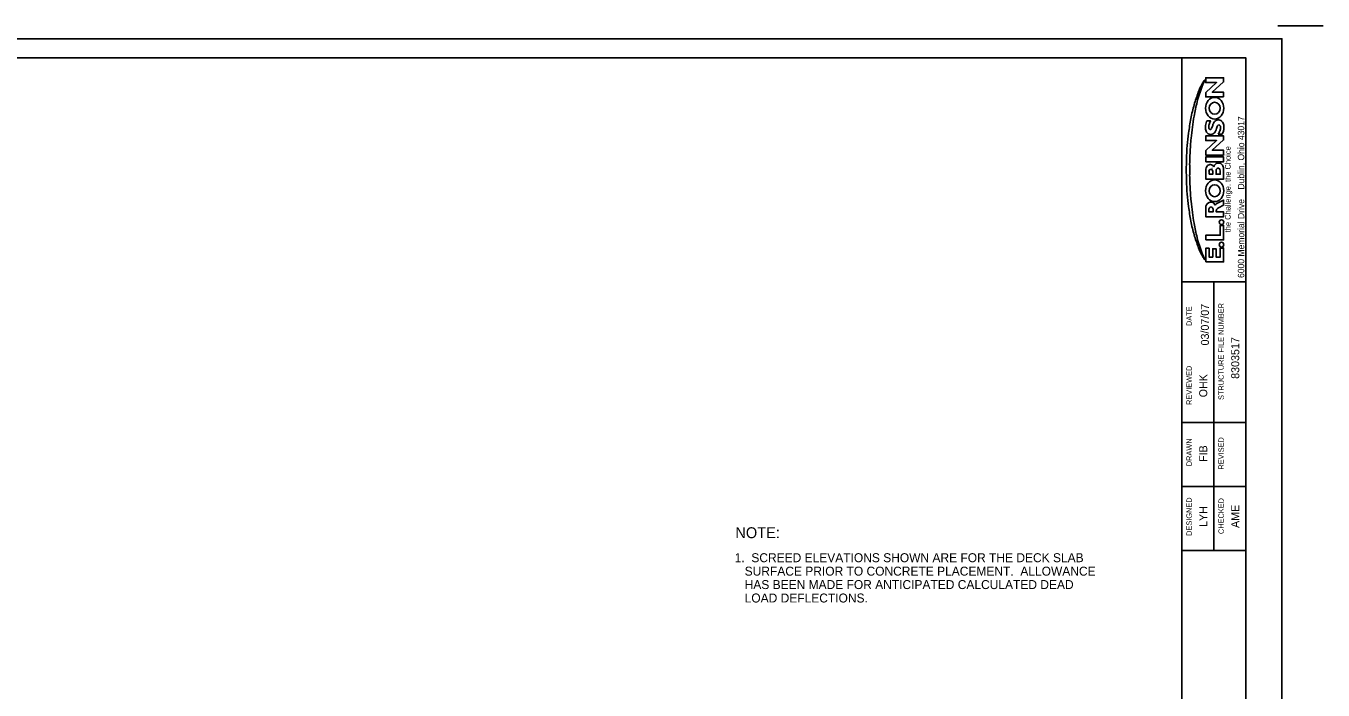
# Model space of a CAD drawing. Extents: x 1466871.1 to 1466907, y 570850.5 to 570872.5.
# Drawn here: x 1466886.76 to 1466907.02, y 570862.08 to 570872.46 of the extents above; entities that cross this region are included whole.
import ezdxf

# ---------------------------------------------------------------- set-up
doc = ezdxf.new("R2010")
doc.units = 0
for name, color, linetype in [('BR_P_Gen_Text', 7, 'Continuous'), ('SH_Border', 7, 'Continuous'), ('SH_Cut_Line', 7, 'Continuous'), ('SH_Data', 7, 'Continuous')]:
    doc.layers.add(name, color=color, linetype=linetype)

msp = doc.modelspace()

# ---------------------------------------------------------------- linework, layer by layer
at = {"layer": 'BR_P_Gen_Text'}
for p, q in [((1466905.443, 570870.773), (1466905.381, 570870.773)), ((1466905.381, 570870.773), (1466905.443, 570870.773)), ((1466905.187, 570870.07), (1466905.187, 570870.205)), ((1466905.238, 570870.19), (1466905.238, 570870.145)), ((1466905.238, 570870.145), (1466905.238, 570870.19)), ((1466905.465, 570870.22), (1466905.465, 570870.07)), ((1466905.465, 570870.07), (1466905.187, 570870.07)), ((1466905.237, 570869.6), (1466905.237, 570869.557)), ((1466905.237, 570869.557), (1466905.237, 570869.6)), ((1466905.237, 570869.557), (1466905.301, 570869.557)), ((1466905.301, 570869.557), (1466905.237, 570869.557)), ((1466905.301, 570869.557), (1466905.301, 570869.6)), ((1466905.301, 570869.6), (1466905.301, 570869.557)), ((1466905.465, 570869.66), (1466905.384, 570869.621)), ((1466905.384, 570869.621), (1466905.465, 570869.66))]:
    msp.add_line(p, q, dxfattribs=at)
for points in [[(1466905.465, 570871.354), (1466905.187, 570871.354), (1466905.187, 570871.423), (1466905.355, 570871.579), (1466905.187, 570871.579), (1466905.187, 570871.654), (1466905.465, 570871.654), (1466905.465, 570871.589), (1466905.288, 570871.428), (1466905.465, 570871.428)], [(1466905.465, 570870.446), (1466905.187, 570870.446), (1466905.187, 570870.515), (1466905.355, 570870.671), (1466905.187, 570870.671), (1466905.187, 570870.745), (1466905.465, 570870.745), (1466905.465, 570870.681), (1466905.288, 570870.52), (1466905.465, 570870.52)], [(1466905.187, 570870.342), (1466905.187, 570870.416), (1466905.465, 570870.416), (1466905.465, 570870.342)], [(1466905.187, 570868.774), (1466905.187, 570868.989), (1466905.238, 570868.989), (1466905.238, 570868.85), (1466905.295, 570868.85), (1466905.295, 570868.981), (1466905.347, 570868.981), (1466905.347, 570868.85), (1466905.414, 570868.85), (1466905.414, 570868.992), (1466905.465, 570868.992), (1466905.465, 570868.774)]]:
    msp.add_lwpolyline(points, close=True, dxfattribs=at)
for points in [[(1466905.205, 570870.981), (1466905.26, 570870.981), (1466905.249, 570870.954)], [(1466905.249, 570870.954), (1466905.26, 570870.981), (1466905.205, 570870.981)], [(1466905.465, 570870.22), (1466905.465, 570870.07), (1466905.187, 570870.07), (1466905.187, 570870.205)], [(1466905.187, 570870.205), (1466905.187, 570870.07), (1466905.465, 570870.07)], [(1466905.238, 570870.145), (1466905.297, 570870.145), (1466905.297, 570870.19)], [(1466905.297, 570870.19), (1466905.297, 570870.145), (1466905.238, 570870.145)], [(1466905.348, 570870.199), (1466905.348, 570870.145), (1466905.414, 570870.145), (1466905.414, 570870.199)], [(1466905.414, 570870.199), (1466905.414, 570870.145), (1466905.348, 570870.145), (1466905.348, 570870.199)], [(1466905.465, 570870.07), (1466905.465, 570870.22)], [(1466905.401, 570869.71), (1466905.465, 570869.742), (1466905.465, 570869.66)], [(1466905.465, 570869.66), (1466905.465, 570869.742), (1466905.401, 570869.71)], [(1466905.352, 570869.579), (1466905.352, 570869.557), (1466905.465, 570869.557), (1466905.465, 570869.482), (1466905.187, 570869.482), (1466905.187, 570869.557), (1466905.187, 570869.621)], [(1466905.187, 570869.621), (1466905.187, 570869.557), (1466905.187, 570869.482), (1466905.465, 570869.482)], [(1466905.237, 570869.6), (1466905.237, 570869.557), (1466905.301, 570869.557), (1466905.301, 570869.6)], [(1466905.465, 570869.482), (1466905.465, 570869.557), (1466905.352, 570869.557), (1466905.352, 570869.579)], [(1466905.187, 570869.118), (1466905.187, 570869.193), (1466905.414, 570869.193), (1466905.414, 570869.345), (1466905.465, 570869.345), (1466905.465, 570869.118), (1466905.187, 570869.118)], [(1466905.465, 570869.345), (1466905.414, 570869.345), (1466905.414, 570869.193), (1466905.187, 570869.193), (1466905.187, 570869.118)], [(1466905.187, 570869.118), (1466905.465, 570869.118), (1466905.465, 570869.345)]]:
    msp.add_lwpolyline(points, dxfattribs=at)
for centre, major_axis, ratio, start_param, end_param in [((1466905.95, 570870.947), (0, 1.141), 0.85, 0.988431, 1.105191), ((1466905.95, 570870.947), (0, 1.141), 0.85, 0.988431, 1.105191), ((1466866.685, 570892.721), (0, 49.953), 0.85, 4.274094, 4.276309), ((1466866.685, 570892.721), (0, 49.953), 0.85, 4.274094, 4.276309), ((1466905.397, 570871.375), (0, 0.363), 0.85, 0.822588, 0.988431), ((1466905.397, 570871.375), (0, 0.363), 0.85, 0.822588, 0.988431), ((1466907.502, 570870.201), (0, 3.112), 0.85, 1.165908, 1.233316), ((1466907.502, 570870.201), (0, 3.112), 0.85, 1.165908, 1.233316), ((1466906.428, 570870.806), (0, 1.685), 0.85, 1.132502, 1.288747), ((1466906.428, 570870.806), (0, 1.685), 0.85, 1.132502, 1.288747), ((1466905.526, 570871.197), (0, 0.583), 0.85, 1.105191, 1.165908), ((1466905.526, 570871.197), (0, 0.583), 0.85, 1.105191, 1.165908), ((1466906.711, 570870.549), (0, 2.119), 0.85, 1.243005, 1.347881), ((1466906.711, 570870.549), (0, 2.119), 0.85, 1.243005, 1.347881), ((1466907.926, 570870.296), (0, 3.52), 0.85, 1.288747, 1.354281), ((1466907.926, 570870.296), (0, 3.52), 0.85, 1.288747, 1.354281), ((1466905.326, 570871.177), (0, -0.0938), 0.910305, 4.71238898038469, 4.712389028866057), ((1466907.9, 570870.279), (0, 3.544), 0.85, 1.360764, 1.426378), ((1466907.9, 570870.279), (0, 3.544), 0.85, 1.360764, 1.426378), ((1466909.145, 570870.102), (0, 4.963), 0.85, 1.378198, 1.448475), ((1466909.145, 570870.102), (0, 4.963), 0.85, 1.378198, 1.448475), ((1466905.357, 570870.878), (0, 0.206), 0.85, 1.108668, 1.320154), ((1466905.357, 570870.878), (0, 0.206), 0.85, 1.108668, 1.320154), ((1466905.066, 570871.048), (0, 0.176), 0.85, 4.250261, 4.3216), ((1466905.066, 570871.048), (0, 0.176), 0.85, 4.250261, 4.3216), ((1466905.399, 570870.868), (0, 0.196), 0.85, 1.114999, 1.297264), ((1466905.399, 570870.868), (0, 0.196), 0.85, 1.114999, 1.297264), ((1466905.484, 570870.822), (0, 0.238), 0.85, 1.030221, 1.254809), ((1466905.484, 570870.822), (0, 0.238), 0.85, 1.030221, 1.254809), ((1466905.39, 570870.888), (0, 0.11), 0.85, 0.486829, 1.030221), ((1466905.39, 570870.888), (0, 0.11), 0.85, 0.486829, 1.030221), ((1466905.326, 570871.177), (0, -0.17), 0.841969, 0, 4.84813681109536e-08), ((1466905.377, 570870.918), (0, 0.0761), 0.85, 0.083326, 0.486829), ((1466905.377, 570870.918), (0, 0.0761), 0.85, 0.083326, 0.486829), ((1466905.383, 570870.841), (0, 0.154), 0.85, 6.083659, 6.366511), ((1466905.383, 570870.841), (0, 0.154), 0.85, 6.083659, 6.366511), ((1466905.396, 570870.919), (0, 0.0741), 0.85, 5.529173, 6.083659), ((1466905.396, 570870.919), (0, 0.0741), 0.85, 5.529173, 6.083659), ((1466905.376, 570870.893), (0, 0.109), 0.85, 4.887723, 5.529173), ((1466905.376, 570870.893), (0, 0.109), 0.85, 4.887723, 5.529174), ((1466906.48, 570870.456), (0, 1.866), 0.85, 1.391456, 1.496401), ((1466906.48, 570870.456), (0, 1.866), 0.85, 1.391456, 1.496401), ((1466905.344, 570870.881), (0, 0.19), 0.85, 1.320154, 1.737094), ((1466905.344, 570870.881), (0, 0.19), 0.85, 1.320154, 1.737094), ((1466905.277, 570870.868), (0, 0.11), 0.85, 1.737094, 2.325359), ((1466905.277, 570870.868), (0, 0.11), 0.85, 1.737094, 2.325359), ((1466905.256, 570870.845), (0, 0.0764), 0.85, 2.325359, 2.878408), ((1466905.256, 570870.845), (0, 0.0764), 0.85, 2.325359, 2.878408), ((1466905.329, 570870.89), (0, 0.111), 0.85, 1.456901, 1.818883), ((1466905.329, 570870.89), (0, 0.111), 0.85, 1.456901, 1.818883), ((1466905.332, 570870.89), (0, 0.115), 0.85, 1.297264, 1.456901), ((1466905.332, 570870.89), (0, 0.115), 0.85, 1.297264, 1.456901), ((1466905.26, 570870.87), (0, 0.0279), 0.85, 1.818883, 2.384672), ((1466905.26, 570870.87), (0, 0.0279), 0.85, 1.818883, 2.384672), ((1466905.264, 570870.881), (0, 0.113), 0.85, 2.878408, 3.55749), ((1466905.264, 570870.881), (0, 0.113), 0.85, 2.878408, 3.55749), ((1466905.255, 570870.864), (0, 0.0197), 0.85, 2.384672, 3.137191), ((1466905.255, 570870.864), (0, 0.0197), 0.85, 2.384672, 3.137191), ((1466905.255, 570870.872), (0, 0.0276), 0.85, 3.137191, 4.01614), ((1466905.255, 570870.872), (0, 0.0276), 0.85, 3.137191, 4.01614), ((1466905.227, 570870.899), (0, 0.071), 0.85, 4.01614, 4.175459), ((1466905.227, 570870.899), (0, 0.071), 0.85, 4.01614, 4.175459), ((1466905.158, 570870.948), (0, 0.165), 0.85, 4.175459, 4.396402), ((1466905.158, 570870.948), (0, 0.165), 0.85, 4.175459, 4.396402), ((1466905.277, 570870.845), (0, 0.0738), 0.85, 3.55749, 3.971659), ((1466905.277, 570870.845), (0, 0.0738), 0.85, 3.55749, 3.971659), ((1466905.233, 570870.893), (0, 0.145), 0.85, 3.971659, 4.353371), ((1466905.233, 570870.893), (0, 0.145), 0.85, 3.971659, 4.353371), ((1466905.968, 570870.568), (0, 0.778), 0.85, 1.164639, 1.211778), ((1466905.968, 570870.568), (0, 0.778), 0.85, 1.164639, 1.211778), ((1466905.581, 570870.764), (0, 0.284), 0.85, 1.063855, 1.164639), ((1466905.581, 570870.764), (0, 0.284), 0.85, 1.063855, 1.164639), ((1466905.393, 570870.887), (0, 0.0304), 0.85, 0.715581, 1.063855), ((1466905.393, 570870.887), (0, 0.0304), 0.85, 0.715581, 1.063855), ((1466905.394, 570870.886), (0, 0.0317), 0.85, 0.212074, 0.715581), ((1466905.394, 570870.886), (0, 0.0317), 0.85, 0.212074, 0.715581), ((1466905.204, 570870.936), (0, 0.265), 0.85, 4.050165, 4.172563), ((1466905.204, 570870.936), (0, 0.265), 0.85, 4.050165, 4.172563), ((1466905.393, 570870.891), (0, 0.026), 0.85, 5.247627, 6.495259), ((1466905.393, 570870.891), (0, 0.026), 0.85, 5.247627, 6.495259), ((1466905.127, 570870.99), (0, 0.37), 0.85, 4.172563, 4.251833), ((1466905.127, 570870.99), (0, 0.37), 0.85, 4.172563, 4.251833), ((1466905.331, 570870.872), (0, 0.103), 0.85, 4.251833, 4.86616), ((1466905.331, 570870.872), (0, 0.103), 0.85, 4.251833, 4.86616), ((1466905.377, 570870.88), (0, 0.0483), 0.85, 4.86616, 5.247627), ((1466905.377, 570870.88), (0, 0.0483), 0.85, 4.86616, 5.247627), ((1466905.338, 570870.862), (0, 0.152), 0.85, 4.087438, 4.318356), ((1466905.338, 570870.862), (0, 0.152), 0.85, 4.087438, 4.318356), ((1466905.322, 570870.87), (0, 0.173), 0.85, 4.318356, 4.51081), ((1466905.322, 570870.87), (0, 0.173), 0.85, 4.318356, 4.51081), ((1466905.296, 570870.877), (0, 0.205), 0.85, 4.51081, 4.887723), ((1466905.296, 570870.877), (0, 0.205), 0.85, 4.51081, 4.887723), ((1466906.681, 570870.355), (0, 2.111), 0.85, 1.456986, 1.558686), ((1466906.681, 570870.355), (0, 2.111), 0.85, 1.456986, 1.558686), ((1466910.743, 570870.035), (0, 6.84), 0.85, 1.472392, 1.505619), ((1466910.743, 570870.035), (0, 6.84), 0.85, 1.472392, 1.505619), ((1466908.489, 570870.162), (0, 4.243), 0.85, 1.519271, 1.558345), ((1466908.489, 570870.162), (0, 4.243), 0.85, 1.519271, 1.558345), ((1466908.287, 570870.224), (0, 3.944), 0.85, 1.505619, 1.553601), ((1466908.287, 570870.224), (0, 3.944), 0.85, 1.505619, 1.553601), ((1466908.489, 570870.268), (0, 4.243), 0.85, 1.583248, 1.622322), ((1466908.489, 570870.268), (0, 4.243), 0.85, 1.583248, 1.622322), ((1466906.837, 570870.253), (0, 2.237), 0.85, 1.553601, 1.587991), ((1466906.837, 570870.253), (0, 2.237), 0.85, 1.553601, 1.587991), ((1466906.837, 570870.176), (0, 2.237), 0.85, 1.553601, 1.587991), ((1466906.837, 570870.176), (0, 2.237), 0.85, 1.553601, 1.587991), ((1466908.287, 570870.206), (0, 3.944), 0.85, 1.587991, 1.635974), ((1466908.287, 570870.206), (0, 3.944), 0.85, 1.587991, 1.635974), ((1466905.292, 570870.203), (0, 0.124), 0.85, 1.228703, 1.558605), ((1466905.292, 570870.203), (0, 0.124), 0.85, 1.228703, 1.558605), ((1466905.292, 570870.203), (0, 0.124), 0.85, 1.228703, 1.558605), ((1466905.259, 570870.214), (0, 0.0833), 0.85, 0.473795, 1.194239), ((1466905.259, 570870.214), (0, 0.0833), 0.85, 0.473795, 1.194239), ((1466905.259, 570870.214), (0, 0.0833), 0.85, 0.473795, 1.194239), ((1466905.256, 570870.228), (0, 0.0696), 0.85, 5.943917, 6.808987), ((1466905.256, 570870.228), (0, 0.0696), 0.85, 5.943917, 6.808987), ((1466905.256, 570870.228), (0, 0.0696), 0.85, 5.943917, 6.808987), ((1466905.266, 570870.188), (0, 0.0337), 0.85, 6.249041, 7.784024), ((1466905.266, 570870.188), (0, 0.0337), 0.85, 6.249041, 7.784024), ((1466905.268, 570870.188), (0, 0.0337), 0.85, 4.782347, 6.317329), ((1466905.268, 570870.188), (0, 0.0337), 0.85, 4.782347, 6.317329), ((1466905.254, 570870.221), (0, 0.0776), 0.85, 5.231996, 5.947796), ((1466905.254, 570870.221), (0, 0.0776), 0.85, 5.231996, 5.947796), ((1466905.254, 570870.221), (0, 0.0776), 0.85, 5.231996, 5.947795), ((1466905.384, 570870.23), (0, 0.0906), 0.85, 0.462144, 1.247207), ((1466905.384, 570870.23), (0, 0.0906), 0.85, 0.462144, 1.247207), ((1466905.384, 570870.23), (0, 0.0906), 0.85, 0.462144, 1.247207), ((1466905.382, 570870.202), (0, 0.0402), 0.85, 0.503186, 1.629765), ((1466905.382, 570870.202), (0, 0.0402), 0.85, 0.503186, 1.629765), ((1466905.385, 570870.222), (0, 0.0982), 0.85, 6.14188, 6.715345), ((1466905.385, 570870.222), (0, 0.0982), 0.85, 6.14188, 6.715345), ((1466905.385, 570870.222), (0, 0.0982), 0.85, 6.14188, 6.715345), ((1466905.381, 570870.206), (0, 0.0358), 0.85, 6.277029, 6.794667), ((1466905.381, 570870.206), (0, 0.0358), 0.85, 6.277029, 6.794667), ((1466905.381, 570870.206), (0, 0.0358), 0.85, 5.771704, 6.289341), ((1466905.381, 570870.206), (0, 0.0358), 0.85, 5.771704, 6.289341), ((1466905.379, 570870.202), (0, 0.0402), 0.85, 4.65342, 5.779999), ((1466905.379, 570870.202), (0, 0.0402), 0.85, 4.65342, 5.779999), ((1466905.389, 570870.231), (0, 0.0885), 0.85, 5.535543, 6.182102), ((1466905.389, 570870.231), (0, 0.0885), 0.85, 5.535543, 6.182102), ((1466905.389, 570870.231), (0, 0.0885), 0.85, 5.535543, 6.182102), ((1466905.394, 570870.235), (0, 0.0818), 0.85, 4.885157, 5.560215), ((1466905.394, 570870.235), (0, 0.0818), 0.85, 4.885157, 5.560215), ((1466905.394, 570870.235), (0, 0.0818), 0.85, 4.885157, 5.560215), ((1466905.294, 570870.212), (0, 0.202), 0.85, 4.750784, 4.89449), ((1466905.294, 570870.212), (0, 0.202), 0.85, 4.750784, 4.89449), ((1466905.294, 570870.212), (0, 0.202), 0.85, 4.750784, 4.89449), ((1466906.681, 570870.075), (0, 2.111), 0.85, 1.582906, 1.684607), ((1466906.681, 570870.075), (0, 2.111), 0.85, 1.582906, 1.684607), ((1466910.743, 570870.394), (0, 6.84), 0.85, 1.635974, 1.669201), ((1466910.743, 570870.394), (0, 6.84), 0.85, 1.635974, 1.669201), ((1466906.48, 570869.973), (0, 1.866), 0.85, 1.645192, 1.750137), ((1466906.48, 570869.973), (0, 1.866), 0.85, 1.645192, 1.750137), ((1466909.145, 570870.328), (0, 4.963), 0.85, 1.693118, 1.763395), ((1466909.145, 570870.328), (0, 4.963), 0.85, 1.693118, 1.763395), ((1466905.326, 570869.888), (0, -0.0938), 0.910305, 4.71238898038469, 4.712389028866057), ((1466905.326, 570869.888), (0, -0.17), 0.841969, 0, 4.84813681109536e-08), ((1466907.9, 570870.151), (0, 3.544), 0.85, 1.715214, 1.780828), ((1466907.9, 570870.151), (0, 3.544), 0.85, 1.715214, 1.780828), ((1466905.263, 570869.62), (0, 0.0895), 0.85, 0.482355, 1.561069), ((1466905.263, 570869.62), (0, 0.0895), 0.85, 0.482355, 1.561069), ((1466905.268, 570869.611), (0, 0.1), 0.85, 6.102437, 6.781247), ((1466905.268, 570869.611), (0, 0.1), 0.85, 6.102437, 6.781247), ((1466905.277, 570869.596), (0, 0.0467), 0.85, 1.002734, 1.50285), ((1466905.277, 570869.596), (0, 0.0467), 0.85, 1.002734, 1.50285), ((1466905.277, 570869.596), (0, 0.0467), 0.85, 1.002734, 1.50285), ((1466905.268, 570869.599), (0, 0.0365), 0.85, 6.259044, 7.205975), ((1466905.268, 570869.599), (0, 0.0365), 0.85, 6.259044, 7.205975), ((1466905.268, 570869.599), (0, 0.0365), 0.85, 6.259044, 7.205975), ((1466905.27, 570869.599), (0, 0.0365), 0.85, 5.360396, 6.307326), ((1466905.27, 570869.599), (0, 0.0365), 0.85, 5.360396, 6.307326), ((1466905.27, 570869.599), (0, 0.0365), 0.85, 5.360396, 6.307326), ((1466905.267, 570869.624), (0, 0.0881), 0.85, 5.152888, 6.061538), ((1466905.267, 570869.624), (0, 0.0881), 0.85, 5.152888, 6.061538), ((1466905.261, 570869.596), (0, 0.0467), 0.85, 4.780335, 5.280452), ((1466905.261, 570869.596), (0, 0.0467), 0.85, 4.780335, 5.280452), ((1466905.261, 570869.596), (0, 0.0467), 0.85, 4.780335, 5.280452), ((1466905.385, 570869.625), (0, 0.069), 0.85, 0.463729, 1.012038), ((1466905.385, 570869.625), (0, 0.069), 0.85, 0.463729, 1.012038), ((1466905.378, 570869.579), (0, 0.0303), 0.85, 0.984544, 1.600686), ((1466905.378, 570869.579), (0, 0.0303), 0.85, 0.984544, 1.600686), ((1466905.401, 570869.56), (0, 0.0643), 0.85, 0.32473, 0.965239), ((1466905.401, 570869.56), (0, 0.0643), 0.85, 0.32473, 0.965239), ((1466905.492, 570869.413), (0, 0.316), 0.85, 0.346308, 0.520291), ((1466905.492, 570869.413), (0, 0.316), 0.85, 0.346308, 0.520291), ((1466906.711, 570869.88), (0, 2.119), 0.85, 1.793712, 1.898588), ((1466906.711, 570869.88), (0, 2.119), 0.85, 1.793712, 1.898588), ((1466907.926, 570870.134), (0, 3.52), 0.85, 1.787312, 1.852845), ((1466907.926, 570870.134), (0, 3.52), 0.85, 1.787312, 1.852845), ((1466905.433, 570869.395), (0, -0.0377), 0.965476, 4.71238898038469, 4.712389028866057), ((1466907.502, 570870.229), (0, 3.112), 0.85, 1.908276, 1.975684), ((1466907.502, 570870.229), (0, 3.112), 0.85, 1.908276, 1.975684), ((1466906.428, 570869.623), (0, 1.685), 0.85, 1.852845, 2.009091), ((1466906.428, 570869.623), (0, 1.685), 0.85, 1.852845, 2.009091), ((1466905.526, 570869.232), (0, 0.583), 0.85, 1.975684, 2.036401), ((1466905.526, 570869.232), (0, 0.583), 0.85, 1.975684, 2.036401), ((1466905.95, 570869.483), (0, 1.141), 0.85, 2.036401, 2.153161), ((1466905.95, 570869.483), (0, 1.141), 0.85, 2.036401, 2.153161), ((1466866.685, 570847.709), (0, 49.953), 0.85, 5.148469, 5.150684), ((1466866.685, 570847.709), (0, 49.953), 0.85, 5.148469, 5.150684), ((1466905.433, 570869.045), (0, -0.0377), 0.965476, 4.71238898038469, 4.712389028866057), ((1466905.397, 570869.055), (0, 0.363), 0.85, 2.153161, 2.319004), ((1466905.397, 570869.055), (0, 0.363), 0.85, 2.153161, 2.319004)]:
    msp.add_ellipse(centre, major_axis=major_axis, ratio=ratio, start_param=start_param, end_param=end_param, dxfattribs=at)
for centre, major_axis, ratio in [((1466905.326, 570871.177), (0, -0.17), 0.841969), ((1466905.326, 570871.177), (0, -0.17), 0.841969), ((1466905.326, 570871.177), (0, -0.0938), 0.910305), ((1466905.326, 570871.177), (0, -0.0938), 0.910305), ((1466905.326, 570869.888), (0, -0.17), 0.841969), ((1466905.326, 570869.888), (0, -0.17), 0.841969), ((1466905.326, 570869.888), (0, -0.0938), 0.910305), ((1466905.326, 570869.888), (0, -0.0938), 0.910305), ((1466905.433, 570869.395), (0, -0.0377), 0.965476), ((1466905.433, 570869.045), (0, -0.0377), 0.965476), ((1466905.433, 570869.045), (0, -0.0377), 0.965476)]:
    msp.add_ellipse(centre, major_axis=major_axis, ratio=ratio, dxfattribs=at)
at = {"layer": 'SH_Border'}
for p, q in [((1466904.814, 570850.964), (1466904.814, 570871.964)), ((1466904.814, 570868.464), (1466905.814, 570868.464)), ((1466905.314, 570864.264), (1466905.314, 570868.464)), ((1466904.814, 570866.264), (1466905.814, 570866.264)), ((1466904.814, 570865.264), (1466905.814, 570865.264)), ((1466904.814, 570864.264), (1466905.814, 570864.264))]:
    msp.add_line(p, q, dxfattribs=at)
msp.add_lwpolyline([(1466874.314, 570871.964), (1466905.814, 570871.964), (1466905.814, 570850.964), (1466874.314, 570850.964)], close=True, dxfattribs=at)
at = {"layer": 'SH_Cut_Line'}
msp.add_line((1466906.314, 570872.464), (1466907.019, 570872.464), dxfattribs=at)
msp.add_lwpolyline([(1466906.376, 570850.614), (1466872.376, 570850.614), (1466872.376, 570872.264), (1466906.376, 570872.264)], close=True, dxfattribs=at)

# ---------------------------------------------------------------- texts
at = {"layer": 'BR_P_Gen_Text'}
for s, height, p in [('6000 Memorial Drive    Dublin, Ohio 43017', 0.1, (1466905.788, 570868.524)), ('the Challenge. the Choice', 0.0875, (1466905.575, 570869.237))]:
    msp.add_text(s, height=height, rotation=90, dxfattribs=at).set_placement(p)
for s, height, p in [('NOTE:', 0.17, (1466897.839, 570864.457)), ('1.  SCREED ELEVATIONS SHOWN ARE FOR THE DECK SLAB ', 0.14, (1466897.828, 570864.081)), ('   SURFACE PRIOR TO CONCRETE PLACEMENT.  ALLOWANCE ', 0.14, (1466897.828, 570863.871)), ('   HAS BEEN MADE FOR ANTICIPATED CALCULATED DEAD ', 0.14, (1466897.828, 570863.661)), ('   LOAD DEFLECTIONS.', 0.14, (1466897.828, 570863.451))]:
    msp.add_text(s, height=height, dxfattribs=at).set_placement(p)
at = {"layer": 'SH_Data'}
for s, height, p in [('.', 0.125, (1466905.297, 570870.218)), ("'", 0.125, (1466905.631, 570870.218)), ('03/07/07', 0.125, (1466905.236, 570867.469)), ('DATE', 0.0833, (1466904.968, 570867.773)), ('STRUCTURE FILE NUMBER', 0.0833, (1466905.468, 570866.617)), ('8303517', 0.125, (1466905.71, 570866.947)), ('REVIEWED', 0.0833, (1466904.968, 570866.539)), ('OHK', 0.125, (1466905.21, 570866.658)), ('DRAWN', 0.0833, (1466904.968, 570865.582)), ('FIB', 0.125, (1466905.21, 570865.649)), ('REVISED', 0.0833, (1466905.468, 570865.53)), ('DESIGNED', 0.0833, (1466904.968, 570864.493)), ('CHECKED', 0.0833, (1466905.468, 570864.521)), ('LYH', 0.125, (1466905.21, 570864.631)), ('AME', 0.125, (1466905.71, 570864.616))]:
    msp.add_text(s, height=height, rotation=90, dxfattribs=at).set_placement(p)

doc.saveas('drawing.dxf')
